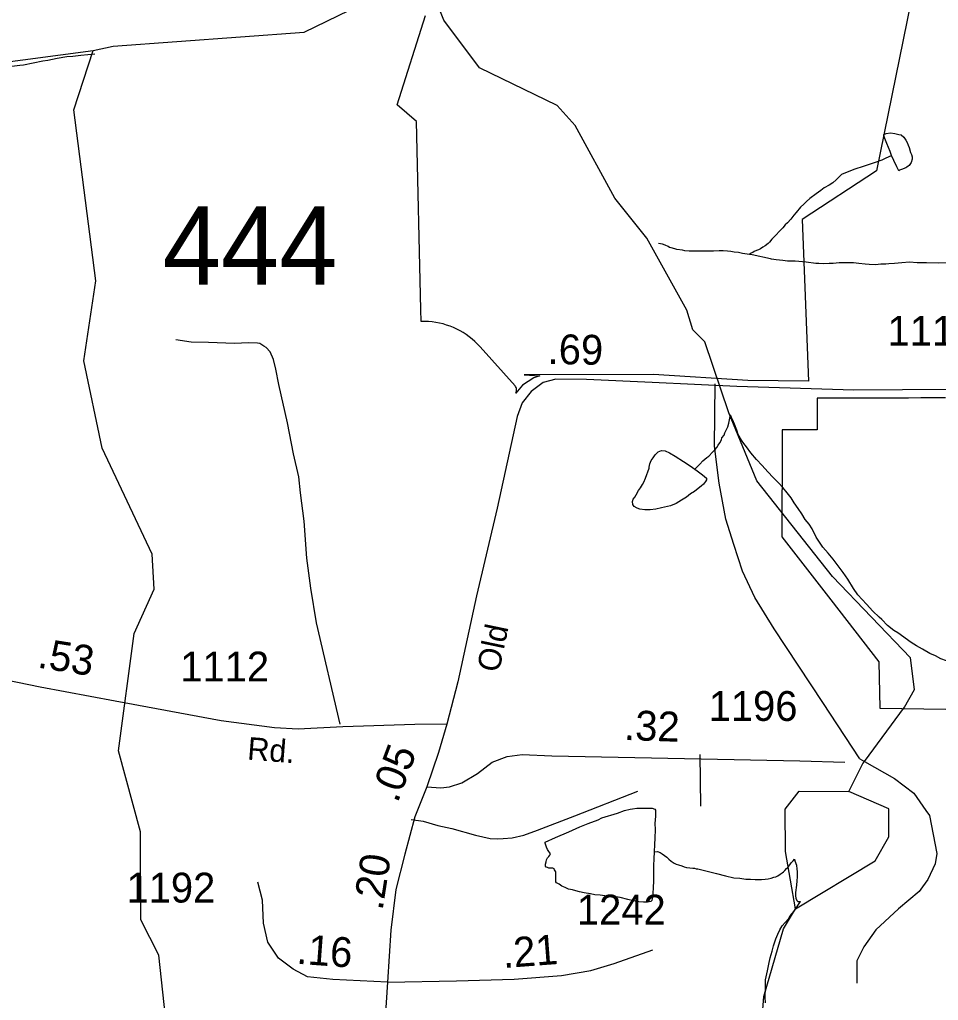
# Model space of a CAD drawing. Extents: x 2001466 to 2224147, y 644118 to 847247.
# Drawn here: x 2051807 to 2055654, y 674778 to 678885 of the extents above; entities that cross this region are included whole.
import ezdxf

# ---------------------------------------------------------------- set-up
doc = ezdxf.new("R2010")
doc.units = 0
for name, color, linetype in [('Exist Boundary Political City Limit New', 7, 'Continuous'), ('Exist Hydrographic Misc Water Feature', 7, 'Continuous'), ('Exist Road Non-System Type 51', 7, 'Continuous'), ('Exist Road Secondary Mileage Hundredths English Label', 7, 'Continuous'), ('Exist Road Secondary Structure Standard Bridge Number Label', 7, 'Continuous'), ('Exist Road Secondary Type 51 Attributed', 7, 'Continuous'), ('Exist Road Secondary Type 51 Label', 7, 'Continuous'), ('Exist Road Secondary Type 51 Number Label', 7, 'Continuous'), ('Map Preparation Boundary City Limit Buffer Line', 7, 'Continuous')]:
    doc.layers.add(name, color=color, linetype=linetype)

msp = doc.modelspace()

# ---------------------------------------------------------------- linework, layer by layer
at = {"layer": 'Exist Boundary Political City Limit New'}
for points in [[(2055571.4, 679117.5), (2055394.8, 678252), (2055084.1, 678047.9), (2055109.6, 677371.6), (2054855.5, 677373.1), (2054461, 677398.2), (2053920.4, 677397.6), (2053985.9, 677393.2), (2053960.6, 677385.2), (2053913.1, 677354.1), (2053884.2, 677321.4), (2053886.1, 677324.9), (2053887.2, 677328.8), (2053887.9, 677332.8), (2053887.9, 677336.8), (2053887.1, 677340.7), (2053885.9, 677344.4), (2053884, 677348), (2053881.5, 677351.2), (2053735, 677515.2), (2053724.5, 677526.4), (2053713.5, 677537.1), (2053702, 677547.2), (2053689.9, 677556.8), (2053677.5, 677565.8), (2053664.6, 677574.2), (2053651.2, 677581.9), (2053637.6, 677588.9), (2053623.6, 677595.4), (2053609.4, 677601.1), (2053594.9, 677606.1), (2053580.1, 677610.4), (2053565.2, 677614.1), (2053550.1, 677616.9), (2053534.9, 677619.1), (2053519.6, 677620.4), (2053504.2, 677621.1), (2053488.9, 677621), (2053487.6, 677671), (2053469.1, 678457.7), (2053387.8, 678527.7), (2053507, 678902)], [(2055684.4, 677301), (2055632.4, 677301.4), (2055580.4, 677300.9), (2055528.4, 677300.4), (2055476.4, 677300), (2055424.4, 677299.6), (2055388.5, 677299.3), (2055372.4, 677299.3), (2055320.5, 677299.2), (2055268.4, 677299.1), (2055266.5, 677299.1), (2055231.6, 677299.2), (2055146.8, 677299.4), (2055146.8, 677294.4), (2055146.5, 677167.4), (2055000, 677167.5), (2054999.9, 677114.2), (2054998.9, 676719.1), (2055203.1, 676455.4), (2055404.2, 676195.8), (2055408.4, 676001.1), (2055685.5, 675998.2)]]:
    msp.add_lwpolyline(points, dxfattribs=at)
at = {"layer": 'Exist Hydrographic Misc Water Feature'}
msp.add_line((2055055.6, 675162), (2055388.6, 675361.9), dxfattribs=at)
for points in [[(2052115.7, 678755.3), (2052199.6, 678773.2), (2052998.7, 678832.5), (2053423.8, 679040.4), (2053523.6, 679126.9)], [(2055344.3, 675779), (2055511.6, 676005.7), (2055553.6, 676080.4), (2055536.6, 676211.9), (2055210.6, 676553.2), (2054893.6, 676953.3), (2054776.7, 677237.9), (2054675.6, 677535.2), (2054625.6, 677585.4), (2054600.5, 677668), (2054433.6, 677970), (2054299.7, 678136.7), (2054132.6, 678441.9), (2054057.6, 678525.5), (2053732.6, 678683.1), (2053582.7, 678882.9), (2053540.6, 678992), (2053523.6, 679126.9)], [(2049126.7, 677999.1), (2049500.7, 678260.5), (2049750.7, 678317.8), (2051083.7, 678497.4), (2051682.7, 678698.5), (2052115.7, 678755.3)], [(2051754, 678689.5), (2051772.1, 678689.6), (2051786, 678691.5), (2051807.9, 678693.5), (2051823.9, 678695.5), (2051904.1, 678711.7), (2051926.1, 678715.7), (2051963.8, 678723.8), (2052005.6, 678730), (2052029.8, 678732), (2052063.6, 678736.2), (2052122.1, 678742)], [(2052033.5, 673507.5), (2052233.4, 673539.6), (2052325.5, 673665.7), (2052365.5, 674265.2), (2052423.5, 674657.7), (2052389.5, 674966.9), (2052314.6, 675116), (2052313.6, 675483.4), (2052221.5, 675823.3), (2052286.5, 676314.1), (2052370.6, 676499.4), (2052361.6, 676647.2), (2052152.6, 677091.1), (2052076.6, 677456.8), (2052126.6, 677790.4), (2052033.7, 678507.6), (2052115.7, 678755.3)], [(2055457.9, 678316.4), (2055451.9, 678332.4), (2055437.6, 678366.2), (2055432, 678380.4), (2055425.7, 678398.4), (2055425.7, 678404.1), (2055435.7, 678408.3), (2055454, 678410.4), (2055471.8, 678408.5), (2055487.8, 678404.4), (2055497.7, 678402.5), (2055509.5, 678392.6), (2055517.7, 678380.4), (2055523.9, 678370.5), (2055527.8, 678358.6), (2055531.7, 678348.7), (2055537.6, 678328.7), (2055541.7, 678320.4), (2055544, 678310.7), (2055543.6, 678300.6), (2055540.1, 678286.6), (2055532.1, 678274.4), (2055528, 678270.6), (2055522.3, 678266.6), (2055518, 678264.4), (2055499.7, 678256.6), (2055491.7, 678254.6), (2055488, 678252.3), (2055483.9, 678260.6), (2055480, 678268.5), (2055467.7, 678294.3), (2055457.9, 678316.4)], [(2055250.2, 678238.1), (2055301.8, 678258.2), (2055344.3, 678272.1), (2055386.1, 678286.4), (2055417.9, 678298.2), (2055435.7, 678306.4), (2055457.9, 678316.4)], [(2055250.2, 678238.1), (2055226.2, 678214.1), (2055212.2, 678202), (2055196, 678191.9), (2055176.1, 678179.9), (2055162.2, 678169.8), (2055142.5, 678155.8), (2055116.3, 678135.8), (2055102.3, 678123.8), (2055090.4, 678111.8), (2055076.5, 678099.7), (2055058.4, 678077.7), (2055048.4, 678065.8), (2055036.3, 678049.8), (2055022.5, 678033.6), (2055012.3, 678025.5), (2055002.2, 678013.6), (2054988.5, 677999.5), (2054972.7, 677981.6), (2054964.5, 677973.5), (2054956.9, 677965.3), (2054946.9, 677953.5), (2054940.7, 677947.5), (2054928.8, 677937.6), (2054918.4, 677931.4), (2054908.5, 677925.6), (2054900.7, 677921.5), (2054892.7, 677917.5), (2054882.7, 677913.3), (2054877, 677909.3), (2054866.5, 677905.2), (2054862.8, 677901.3)], [(2054862.8, 677901.3), (2054834.5, 677905.2), (2054816.5, 677909.2), (2054798.6, 677911.1), (2054784.5, 677913.2), (2054770.7, 677915.3), (2054752.9, 677917.2), (2054736.7, 677917.2), (2054712.5, 677915.2), (2054702.9, 677915.1), (2054693, 677914.9), (2054676.8, 677914.9), (2054660.6, 677915), (2054653, 677914.8), (2054630.5, 677915.1), (2054611, 677914.7), (2054592.6, 677916.7), (2054582.7, 677919.1), (2054558.7, 677922.7), (2054550.5, 677924.7), (2054534.7, 677928.8), (2054528.6, 677930.9), (2054522.8, 677934.6), (2054510.7, 677940.5), (2054499, 677944.7), (2054482.8, 677946.8)], [(2055764.6, 677867.2), (2055652.5, 677864.7), (2055604.7, 677866.7), (2055564.7, 677866.7), (2055532.9, 677868.7), (2055500.5, 677866.7), (2055470.8, 677864.3), (2055446.8, 677862.7), (2055434.5, 677860.5), (2055413, 677860.5), (2055390.8, 677858.2), (2055364.8, 677860.1), (2055346.9, 677860.4), (2055320.9, 677864.3), (2055298.5, 677866), (2055268.8, 677866.1), (2055238.7, 677866.2), (2055212.8, 677864), (2055196.6, 677864.1), (2055174.7, 677862.2), (2055153, 677863.8), (2055140.7, 677864), (2055100.7, 677869.7), (2055054.7, 677873.8), (2055022.8, 677873.8), (2055002.7, 677875.6), (2054974.8, 677879.5), (2054954.9, 677881.7), (2054950.8, 677883.5), (2054874.9, 677899.5), (2054862.8, 677901.3)], [(2054634.4, 677003), (2054642.2, 677011.2), (2054654.5, 677023.1), (2054668.2, 677037.3), (2054684.6, 677051), (2054692.4, 677057.2), (2054708.2, 677073.4), (2054718.5, 677083.2), (2054726.5, 677093.4), (2054732.4, 677103.4), (2054738.3, 677113), (2054746.1, 677125.2), (2054748, 677133.1), (2054756.4, 677145.2), (2054760.1, 677155.2), (2054764.2, 677163.5), (2054772.2, 677179.3), (2054776.3, 677195.3), (2054784.1, 677229.4)], [(2055561.8, 676263), (2055539.5, 676276.9), (2055483.7, 676316.6), (2055467.5, 676326.8), (2055441.3, 676348.6), (2055417.3, 676372.5), (2055405.4, 676382.8), (2055379.5, 676408.6), (2055353.1, 676436.6), (2055317.4, 676476.5), (2055299.2, 676502.3), (2055275.2, 676542.5), (2055255.1, 676570.3), (2055213, 676626.1), (2055192.9, 676650.3), (2055170.8, 676675.9), (2055142.9, 676718.3), (2055124.9, 676752.3), (2055112.8, 676771.9), (2055096.6, 676792.2), (2055082.8, 676815.8), (2055066.4, 676838.2), (2055050.4, 676862.1), (2055036.9, 676882), (2055020.5, 676903.9), (2055002.5, 676925.8), (2054984.6, 676945.9), (2054962.3, 676967.6), (2054940.3, 676991.6), (2054916.1, 677017.5), (2054891.9, 677043.5), (2054868.1, 677071.5), (2054850.5, 677095.6), (2054840.1, 677109.4), (2054830, 677123.5), (2054816.3, 677147.5), (2054810.3, 677165.4), (2054800.3, 677191.3), (2054793.9, 677207.2), (2054788, 677219.5), (2054784.1, 677229.4)], [(2054634.4, 677003), (2054644.6, 676995), (2054666.6, 676979.1), (2054682.6, 676965.4), (2054682.6, 676957.3), (2054678.7, 676951.4), (2054670.7, 676939.2), (2054660.2, 676931), (2054648.5, 676921), (2054632.5, 676909.3), (2054616.7, 676899.1), (2054598.7, 676885.2), (2054578.8, 676873.2), (2054556.5, 676859.1), (2054532.7, 676848.9), (2054494.7, 676840.9), (2054470.8, 676834.8), (2054446.8, 676832.8), (2054425, 676832.8), (2054404.5, 676834.7), (2054392.4, 676838.6), (2054380.5, 676846.5), (2054374.8, 676854.6), (2054372.9, 676866.7), (2054376.6, 676876.7), (2054382.6, 676884.7), (2054388.5, 676894.7), (2054398.4, 676912.7), (2054406.8, 676924.8), (2054414.6, 676938.6), (2054420.5, 676948.7), (2054428.3, 676964.5), (2054442.5, 677006.6), (2054442.5, 677010.7), (2054446.4, 677024.7), (2054452.1, 677038.8), (2054460.1, 677050.6), (2054468.5, 677062.7), (2054480.2, 677074.7), (2054494.3, 677080.6), (2054510.3, 677079.1), (2054528.6, 677071.1), (2054552.6, 677056.9), (2054586.2, 677035.1), (2054614.3, 677017.1), (2054634.4, 677003)], [(2055729.8, 676181.1), (2055715.8, 676187.3), (2055687.7, 676199.3), (2055663.7, 676209), (2055641.6, 676221.3), (2055617.6, 676231), (2055587.5, 676249), (2055561.8, 676263)], [(2055279.5, 675652.9), (2055337.5, 675769.8), (2055344.3, 675779)], [(2055055.6, 675162), (2055013.5, 675402.3), (2055012.5, 675579.5), (2055071.6, 675653.8), (2055279.5, 675652.9)], [(2055388.6, 675361.9), (2055446.6, 675462.5), (2055446.6, 675580.5), (2055279.5, 675652.9)], [(2054463.4, 675400.9), (2054463.2, 675370.9), (2054461.5, 675343.2), (2054461.5, 675320.9), (2054461.5, 675295), (2054461.7, 675273), (2054459.5, 675255.1), (2054457.8, 675221.3), (2054453.7, 675197.1), (2054449.6, 675192.9), (2054435.7, 675188.9), (2054419.7, 675188.9), (2054399.6, 675191.1), (2054377.7, 675194.9), (2054353.7, 675201), (2054321.9, 675209), (2054295.6, 675213), (2054277.8, 675214.9), (2054257.7, 675216.7), (2054237.6, 675218.6), (2054215.9, 675220.7), (2054197.8, 675224.6), (2054171.6, 675228.6), (2054151.9, 675232.4), (2054135.5, 675236.5), (2054121.8, 675240.6), (2054106, 675244.6), (2054091.6, 675250.5), (2054077.7, 675256.2), (2054065.8, 675264.5), (2054055.7, 675270.5), (2054051.8, 675274.3), (2054051.6, 675278.4), (2054051.8, 675284.5), (2054051.8, 675292.2), (2054051.8, 675302.3), (2054051.8, 675310.4), (2054051.6, 675316.5), (2054047.3, 675324.5), (2054045.5, 675328.4), (2054039.7, 675332.1), (2054031.5, 675332.1), (2054023.5, 675332.2), (2054017.6, 675334.3), (2054011.4, 675336.4), (2054009.6, 675340.3), (2054009.6, 675348.4), (2054011.4, 675358.3), (2054013.5, 675366.1), (2054017.4, 675374.5), (2054023.5, 675380.4), (2054027.4, 675386.3), (2054029.3, 675392.5), (2054027.4, 675396), (2054023.3, 675402.3), (2054017.4, 675410.1), (2054013.5, 675420), (2054009.2, 675432.1), (2054007.3, 675436.4), (2054007.1, 675440.5), (2054051.2, 675460.2), (2054107.2, 675484.5), (2054152.9, 675504.4), (2054187.2, 675518.7), (2054229, 675534.6), (2054244.8, 675542.8), (2054311, 675562.7), (2054339.1, 675572.7), (2054363.1, 675578.8), (2054373.1, 675580.9), (2054391, 675583), (2054407.2, 675583), (2054437.3, 675582.9), (2054455.2, 675583), (2054467.3, 675579.2), (2054469.1, 675575.3), (2054469.1, 675548.9), (2054467.1, 675519.2), (2054467.5, 675493.2), (2054467.3, 675457.1), (2054465, 675431.1), (2054463.4, 675400.9)], [(2054463.4, 675400.9), (2054477.5, 675401.2), (2054489.6, 675397), (2054497.6, 675391.3), (2054507.3, 675385.4), (2054517.3, 675377.3), (2054525.3, 675369.2), (2054535.5, 675361.2), (2054547.4, 675353.3), (2054555.6, 675349.2), (2054565.5, 675345.3), (2054579.2, 675341.1), (2054589.3, 675337.2), (2054599.5, 675335.2), (2054613.3, 675333.6), (2054625.4, 675331.3), (2054633.4, 675331.3), (2054639.5, 675329.6), (2054647.5, 675329.6)], [(2054647.5, 675329.6), (2054725.4, 675309.7), (2054763.2, 675299.5), (2054797.2, 675291.9), (2054823.2, 675290), (2054847.2, 675285.9), (2054867.5, 675285.7), (2054887.2, 675283.9), (2054905.7, 675284), (2054913.7, 675284), (2054929.2, 675286.1), (2054941.6, 675287.9), (2054953.4, 675290.1), (2054965.5, 675294), (2054973.5, 675296), (2054981.3, 675300.1), (2054991.4, 675306.3), (2054999.6, 675311.9), (2055005.7, 675315.9), (2055011.5, 675322.3), (2055017.4, 675330.3), (2055023.2, 675334.3), (2055031.6, 675346), (2055037.1, 675354.1), (2055045.3, 675362.2), (2055051.3, 675370.2)], [(2055051.3, 675370.2), (2055053.3, 675362.2), (2055059.3, 675344.2), (2055061.3, 675328.1), (2055063.4, 675318.1), (2055063.4, 675310.3), (2055063.1, 675296.2), (2055061.5, 675278.2), (2055059.3, 675260.2), (2055055.6, 675230), (2055055.6, 675220.3), (2055055.4, 675216.3), (2055057.6, 675206.2), (2055061.3, 675196.3), (2055065.4, 675192.4), (2055077.3, 675192.2)], [(2054890.5, 673961.3), (2054940.5, 674078.3), (2054931.5, 674387), (2054898.5, 674463.1), (2054922.5, 674794), (2055005.5, 675077.7), (2055055.6, 675162)], [(2054930.5, 674767.9), (2054928.2, 674790.2), (2054930.5, 674834), (2054929.9, 674864.1), (2054938.1, 674902.3), (2054944, 674930.2), (2054950, 674956.1), (2054958, 674984), (2054963.9, 675006.2), (2054973.9, 675036), (2054981.9, 675056.2), (2054989.5, 675074.1), (2055000, 675090), (2055012.1, 675104), (2055025.8, 675120.1), (2055033.8, 675132.3), (2055049.8, 675152.2), (2055077.3, 675192.2)]]:
    msp.add_lwpolyline(points, dxfattribs=at)
at = {"layer": 'Exist Road Non-System Type 51'}
for p, q in [((2054660, 675591.9), (2054656.6, 675807.2)), ((2055324.6, 675790.2), (2055344.3, 675779))]:
    msp.add_line(p, q, dxfattribs=at)
for points in [[(2053149.2, 675935.5), (2053049.8, 676359.5), (2053026.7, 676503.9), (2053009.3, 676630.3), (2052998.4, 676784.5), (2052982.8, 676902.8), (2052976.2, 676971), (2052954.2, 677067.4), (2052928.8, 677195.9), (2052892.1, 677356.7), (2052879.4, 677420.9), (2052870.2, 677461.1), (2052856.8, 677493.4), (2052839.2, 677511.8), (2052829.3, 677518), (2052813.6, 677528.3), (2052803.6, 677530.5), (2052765.6, 677531.3), (2052707.6, 677528.4), (2052597.6, 677532.7), (2052525.7, 677534.1), (2052461.9, 677543.4)], [(2055324.6, 675790.2), (2055169.7, 676025.4), (2054966.7, 676334.1), (2054886.1, 676464.8), (2054833.3, 676576), (2054797.1, 676687.3), (2054763.8, 676793), (2054735.9, 676943.2), (2054716.5, 677098.9), (2054719.7, 677359.9)], [(2055344.3, 675779), (2055470.3, 675707.8), (2055551.7, 675646.2), (2055601.7, 675573.9)], [(2053446.2, 675535.7), (2053496.8, 675528.4), (2053558.5, 675511.1), (2053616.2, 675498), (2053715.7, 675470), (2053777.4, 675456.7), (2053809.3, 675454), (2053831.4, 675455.6), (2053869.4, 675458.8), (2053917.7, 675469.8), (2053976.1, 675490.7), (2054131.3, 675551.5), (2054395.4, 675654.2)], [(2055601.7, 675573.9), (2055616.8, 675552.1), (2055647.6, 675392.8), (2055640.3, 675349.4), (2055609.6, 675284.3), (2055587.4, 675253.3)], [(2055587.4, 675253.3), (2055573.4, 675233.6), (2055486.6, 675161.2), (2055392.5, 675074.3), (2055341.9, 675001.9), (2055312.9, 674944), (2055312.9, 674849.9)]]:
    msp.add_lwpolyline(points, dxfattribs=at)
at = {"layer": 'Exist Road Secondary Type 51 Attributed'}
for points in [[(2057289.7, 677288.9), (2057114.3, 677295.4), (2056848.8, 677306), (2056448.2, 677325), (2055935.2, 677339.8), (2055707.2, 677336.6), (2055300.3, 677333.5), (2054810.5, 677348.2), (2054455.8, 677365.1), (2054180.3, 677377.8), (2054052.6, 677379.9), (2053999.8, 677365.1), (2053949.1, 677327.1), (2053911.1, 677280.6), (2053890.5, 677223.6), (2053806.1, 676839.1), (2053720.6, 676471.5), (2053642.5, 676112.4), (2053595.5, 675934.9)], [(2053595.5, 675934.9), (2053462.5, 675933.8), (2053160.6, 675923.3), (2052973.2, 675913.8), (2052875.1, 675920.1), (2052651.3, 675948.6), (2052207.4, 676031), (2051892.8, 676090.2), (2051750.9, 676119.7), (2051633.7, 676129.3), (2051508.1, 676129.3), (2051350.8, 676117.6), (2050999.8, 676070.1), (2050833, 676057.4), (2050804.5, 676057.2)], [(2053595.5, 675934.9), (2053561.7, 675816.6), (2053512.6, 675672.9)], [(2053512.6, 675672.9), (2053570.7, 675667.6), (2053606.6, 675672.9), (2053658.3, 675689.8), (2053724.8, 675727.9), (2053786, 675775.4), (2053848.3, 675799.7), (2053911.6, 675807.1), (2054035.1, 675801.8), (2054660.6, 675790.2), (2055073.8, 675781.7), (2055262.8, 675775.4)], [(2053512.6, 675672.9), (2053462.5, 675546.2), (2053420.3, 675389.8), (2053382.3, 675241.9), (2053361.2, 675072.9), (2053348, 674854.3)], [(2053348, 674854.3), (2053118.9, 674865.9), (2053012.3, 674876.5), (2052952.1, 674909.2), (2052890.9, 674954.6), (2052847.1, 675022.2), (2052828.1, 675101.5), (2052823.9, 675197.6), (2052804.9, 675273.6)], [(2053348, 674854.3), (2053636, 674860), (2053878.1, 674867.5), (2054075.4, 674882.4), (2054198.3, 674902.9), (2054297, 674932.7), (2054459, 674990.5)], [(2053348, 674854.3), (2053337.9, 674705.3), (2053322.1, 674483.5), (2053273, 674208.9), (2053241.4, 673918.4), (2053213.4, 673814.9), (2053181.7, 673744.1), (2053135.3, 673688.1), (2053067.7, 673645.9), (2052973.8, 673620.5), (2052884, 673607.8), (2052733.6, 673592), (2052560.5, 673552.9), (2052193.2, 673447.3), (2052009, 673402.9), (2051909.7, 673386), (2051763, 673373.3), (2051706, 673358.5), (2051668, 673331.1), (2051637.4, 673286.7), (2051606.8, 673177.9), (2051542.9, 672907.5), (2051504, 672757.5)]]:
    msp.add_lwpolyline(points, dxfattribs=at)
at = {"layer": 'Map Preparation Boundary City Limit Buffer Line'}
for points in [[(2055571.4, 679117.5), (2055394.8, 678252), (2055084.1, 678047.9), (2055109.6, 677371.6), (2054855.5, 677373.1), (2054461, 677398.2), (2053920.4, 677397.6), (2053985.9, 677393.2), (2053960.6, 677385.2), (2053913.1, 677354.1), (2053884.2, 677321.4), (2053886.1, 677324.9), (2053887.2, 677328.8), (2053887.9, 677332.8), (2053887.9, 677336.8), (2053887.1, 677340.7), (2053885.9, 677344.4), (2053884, 677348), (2053881.5, 677351.2), (2053735, 677515.2), (2053724.5, 677526.4), (2053713.5, 677537.1), (2053702, 677547.2), (2053689.9, 677556.8), (2053677.5, 677565.8), (2053664.6, 677574.2), (2053651.2, 677581.9), (2053637.6, 677588.9), (2053623.6, 677595.4), (2053609.4, 677601.1), (2053594.9, 677606.1), (2053580.1, 677610.4), (2053565.2, 677614.1), (2053550.1, 677616.9), (2053534.9, 677619.1), (2053519.6, 677620.4), (2053504.2, 677621.1), (2053488.9, 677621), (2053487.6, 677671), (2053469.1, 678457.7), (2053387.8, 678527.7), (2053507, 678902)], [(2055684.4, 677301), (2055632.4, 677301.4), (2055580.4, 677300.9), (2055528.4, 677300.4), (2055476.4, 677300), (2055424.4, 677299.6), (2055388.5, 677299.3), (2055372.4, 677299.3), (2055320.5, 677299.2), (2055268.4, 677299.1), (2055266.5, 677299.1), (2055231.6, 677299.2), (2055146.8, 677299.4), (2055146.8, 677294.4), (2055146.5, 677167.4), (2055000, 677167.5), (2054999.9, 677114.2), (2054998.9, 676719.1), (2055203.1, 676455.4), (2055404.2, 676195.8), (2055408.4, 676001.1), (2055685.5, 675998.2)]]:
    msp.add_lwpolyline(points, dxfattribs=at)

# ---------------------------------------------------------------- texts
at = {"layer": 'Exist Road Secondary Mileage Hundredths English Label'}
for s, rotation, p in [('.69', 359.0523, (2054017.1, 677443)), ('.53', 351.0184, (2051878.5, 676172.3)), ('.32', 358.0463, (2054336.6, 675868.8)), ('.05', 69.3692, (2053389.5, 675601.3)), ('.20', 81.1435, (2053326.5, 675151.7)), ('.16', 355.8158, (2052964.4, 674932)), ('.21', 4.3189, (2053832.9, 674913.4))]:
    msp.add_text(s, height=125, rotation=rotation, dxfattribs=at).set_placement(p)
at = {"layer": 'Exist Road Secondary Structure Standard Bridge Number Label'}
msp.add_text('444', height=328.08, dxfattribs=at).set_placement((2052406.2, 677774.7))
at = {"layer": 'Exist Road Secondary Type 51 Label'}
for s, rotation, p in [('Old', 78.1407, (2053814.1, 676147.9)), ('Rd.', 355.5352, (2052758.4, 675786.6))]:
    msp.add_text(s, height=95, rotation=rotation, dxfattribs=at).set_placement(p)
at = {"layer": 'Exist Road Secondary Type 51 Number Label'}
for s, p in [('1111', (2055441.1, 677519.4)), ('1112', (2052479.9, 676113.5)), ('1196', (2054692.2, 675948.4)), ('1192', (2052254.7, 675187.9)), ('1242', (2054140.5, 675095.7))]:
    msp.add_text(s, height=125, dxfattribs=at).set_placement(p)

doc.saveas('drawing.dxf')
